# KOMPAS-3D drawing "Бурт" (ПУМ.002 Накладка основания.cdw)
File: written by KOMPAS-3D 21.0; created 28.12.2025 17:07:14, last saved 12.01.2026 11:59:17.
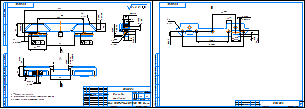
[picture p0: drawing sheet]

Sheets 1-2: A4x2, landscape

Document properties: Автор: User; Знак неуказанной шероховатости: 4; Параметр неуказанной шероховатости: Ra 2.5; Масса: 0.258544; Форматы листов документа: 2xA4@4~2; Полное имя файла: ..\ПУМ.002 Накладка основания.m3d

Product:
- Part/product: Бурт
    Материал: АМг6  ГОСТ 4784-2019 (density 2650 kg/m3)
    Масса: 0.258544
    Форматы листов документа: 2xA4@4~2

Title block, sheet 1: Наименование: Накладка / основания; designation: ПУМ.002; Материал: АМг6  ГОСТ 4784-2019; Масса: 0,26; sheet number: 1; Количество листов документа: 2; organisation: ООО ТПК Пегас; Форматы листов документа: A4 2; stored path: C:\Users\Гузель\Desktop\ПУМ\Чертежи\ПУМ.002 Накладка основания.cdw; Разработал: Гайсин
Title block, sheet 2: sheet number: 2

Views: Вид 1, Местный разрез 1, Сверху, Проекционный вид 2, Вид по стрелке А, Вид по стрелке 4, Вид по стрелке Б
Referenced files in C:\Users\Гузель\Desktop\ПУМ\: ПУМ.002 Накладка основания.m3d
Referenced files in C:\Users\User\Desktop\ПУ\ПУМ\: ПУМ.002 Накладка основания.m3d
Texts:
  Бурт
  max
  по контуру
  Ra 2.5
  Ra 2.5 ( )
Dimensions and other numbers on the sheet: 200; 36; 22; 18; 4 места; 25,5±0,1; 128; 11; 2 места; 50; 78; 0,1; 2; 8 рад; 9±0,1; 10±0,1; 3; 2 фаски; 4; 12; -7Н; 6; 5 отв; 5; 2 отв; 56; 27; 14; 8; 168±0,1; 90±0,1; 13±0,1; 64; 24; 2,5; 8 фасок; 4 рад; 1:1; 0,26; 1

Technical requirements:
  * Размер для справок
  Неуказанные предельные отклонения  0,2 мм
  Острые кромки притупить 0,2х45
